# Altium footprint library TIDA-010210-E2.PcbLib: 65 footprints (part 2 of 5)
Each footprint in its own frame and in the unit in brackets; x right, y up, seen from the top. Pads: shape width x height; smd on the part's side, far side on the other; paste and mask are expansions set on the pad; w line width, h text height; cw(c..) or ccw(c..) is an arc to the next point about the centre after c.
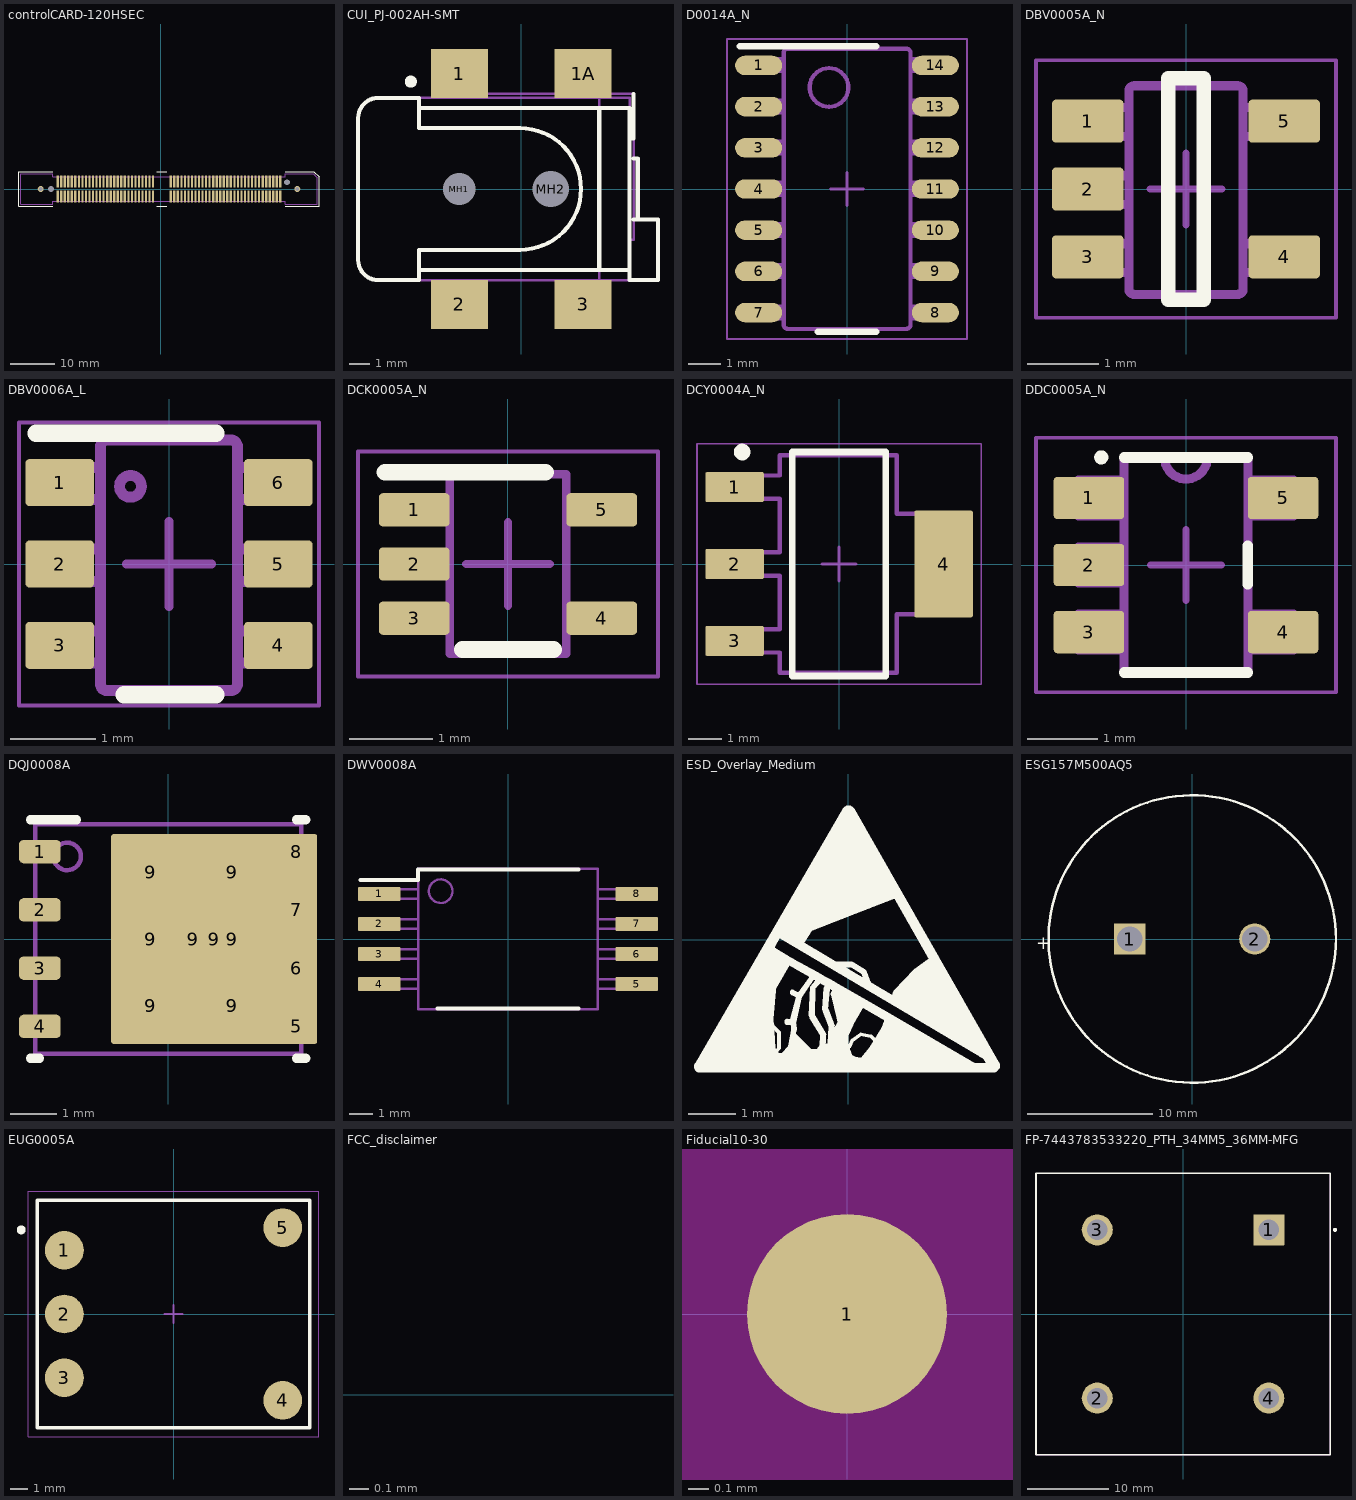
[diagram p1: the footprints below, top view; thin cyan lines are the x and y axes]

## controlCARD-120HSEC [mm] "Pads are not numbered according to Samtec datasheet."
height 7.13
pads (124):
  rect 0.5x2.724 smd: 1(-23.357,-1.678) 2(-23.357,1.722) 3(-22.557,-1.678) 4(-22.557,1.722) 5(-21.757,-1.678) 6(-21.757,1.722) 7(-20.957,-1.678) 8(-20.957,1.722) 9(-20.157,-1.678) 10(-20.157,1.722) 11(-19.357,-1.678) 12(-19.357,1.722) 13(-18.557,-1.678) 14(-18.557,1.722) 15(-17.757,-1.678) 16(-17.757,1.722) 17(-16.957,-1.678) 18(-16.957,1.722) 19(-16.157,-1.678) 20(-16.157,1.722) 21(-15.357,-1.678) 22(-15.357,1.722) 23(-14.557,-1.678) 24(-14.557,1.722) 25(-13.757,-1.678) 26(-13.757,1.722) 27(-12.957,-1.678) 28(-12.957,1.722) 29(-12.157,-1.678) 30(-12.157,1.722) 31(-11.357,-1.678) 32(-11.357,1.722) 33(-10.557,-1.678) 34(-10.557,1.722) 35(-9.757,-1.678) 36(-9.757,1.722) 37(-8.957,-1.678) 38(-8.957,1.722) 39(-8.157,-1.678) 40(-8.157,1.722) 41(-7.357,-1.678) 42(-7.357,1.722) 43(-6.557,-1.678) 44(-6.557,1.722) 45(-5.757,-1.678) 46(-5.757,1.722) 47(-4.957,-1.678) 48(-4.957,1.722) 49(-4.157,-1.678) 50(-4.157,1.722) 51(-3.357,-1.678) 52(-3.357,1.722) 53(-2.557,-1.678) 54(-2.557,1.722) 55(-1.757,-1.678) 56(-1.757,1.722) 57(2.243,-1.678) 58(2.243,1.722) 59(3.043,-1.678) 60(3.043,1.722) 61(3.843,-1.678) 62(3.843,1.722) 63(4.643,-1.678) 64(4.643,1.722) 65(5.443,-1.678) 66(5.443,1.722) 67(6.243,-1.678) 68(6.243,1.722) 69(7.043,-1.678) 70(7.043,1.722) 71(7.843,-1.678) 72(7.843,1.722) 73(8.643,-1.678) 74(8.643,1.722) 75(9.443,-1.678) 76(9.443,1.722) 77(10.243,-1.678) 78(10.243,1.722) 79(11.043,-1.678) 80(11.043,1.722) 81(11.843,-1.678) 82(11.843,1.722) 83(12.643,-1.678) 84(12.643,1.722) 85(13.443,-1.678) 86(13.443,1.722) 87(14.243,-1.678) 88(14.243,1.722) 89(15.043,-1.678) 90(15.043,1.722) 91(15.843,-1.678) 92(15.843,1.722) 93(16.643,-1.678) 94(16.643,1.722) 95(17.443,-1.678) 96(17.443,1.722) 97(18.243,-1.678) 98(18.243,1.722) 99(19.043,-1.678) 100(19.043,1.722) 101(19.843,-1.678) 102(19.843,1.722) 103(20.643,-1.678) 104(20.643,1.722) 105(21.443,-1.678) 106(21.443,1.722) 107(22.243,-1.678) 108(22.243,1.722) 109(23.043,-1.678) 110(23.043,1.722) 111(23.843,-1.678) 112(23.843,1.722) 113(24.643,-1.678) 114(24.643,1.722) 115(25.443,-1.678) 116(25.443,1.722) 117(26.243,-1.678) 118(26.243,1.722) 119(27.043,-1.678) 120(27.043,1.722)
  round 0.025 hole 1.27 unplated mask+0.876: 181(-24.857,0.022) 182(28.543,1.522)
  round 1.348 hole 0.84: 185(-27.207,0.022) 186(30.893,0.022)
Top Overlay:
  lines w0.254: -24.457,-3.859 -32.113,-3.859 -32.113,3.903 -24.457,3.903 ; -0.876,-3.859 1.362,-3.859 ; -0.876,3.903 1.362,3.903 ; 28.143,-3.859 35.799,-3.859 35.799,2.76 34.656,3.903 28.143,3.903
Mechanical 5:
  lines w0.1: -31.732,-3.478 -24.457,-3.478 -24.457,-2.778 28.143,-2.778 28.143,-3.478 35.418,-3.478 35.418,2.547 34.443,3.522 28.143,3.522 28.143,2.822 -24.457,2.822 -24.457,3.522 -31.732,3.522 -31.732,-3.478
  text ".Designator" at -1.1,-0.4 h1.02
3D body "Samtec-HSEC8-160-01-L-DV-A-BL.stp": height 12.35, standoff -1.35, extent -31.75,-3.475 35.3,3.525

## CUI_PJ-002AH-SMT [mm] "CUI"
height 11.2
pads (6):
  rect 2.8x2.4 smd: 1(-3.05,5.7) 1A(3.05,5.7) 2(-3.05,-5.7) 3(3.05,-5.7)
  round 1 hole 1.6 unplated: MH1(-3.05,0)
  round 1.524 hole 1.8 unplated: MH2(1.45,0)
Top Overlay:
  circle w0.3: c-5.45,5.3 r0.15
  lines w0.2: -7.782,4.181 cw(c-7.048,3.497) -7.467,4.409 ; -7.467,-4.409 ccw(c-7.05,-3.5) -7.337,-4.458 ccw(c-7.048,-3.492) -7.185,-4.491 ccw(c-7.05,-3.5) -7.05,-4.5 -5.05,-4.5 -5.05,-4.3 -5.05,-3 -0.05,-3 ccw(c-0.05,0) 2.95,0 ccw(c-0.05,0) -0.05,3 -5.05,3 -5.05,4.3 -5.05,4.5 -7.05,4.5 ccw(c-7.05,3.5) -7.165,4.493 ccw(c-7.048,3.491) -7.36,4.451 ccw(c-7.05,3.5) -7.426,4.427 ccw(c-7.048,3.498) -7.786,4.176 ccw(c-7.05,3.5) -8.05,3.5 -8.05,-3.5 ccw(c-7.05,-3.5) -7.782,-4.181 ccw(c-7.048,-3.498) -7.467,-4.409 ; -7.336,4.458 cw(c-7.048,3.492) -7.185,4.491 ; -5.05,-4 3.85,-4 ; -5.05,4 3.85,4 ; 5.35,2.5 5.55,2.5 5.55,4.7 ; 5.55,-1.5 5.75,-1.5 ; 5.55,1.5 5.75,1.5 5.75,-1.5 ; 3.85,-4 3.85,4 ; 3.85,-4 5.35,-4 ; 3.85,-4 3.85,4 ; 3.85,4 5.35,4 5.35,-4 ; 5.35,-4 5.35,-4.5 6.75,-4.5 6.75,-1.5 5.75,-1.5 ; -7.786,-4.177 ccw(c-7.05,-3.5) -7.426,-4.427 cw(c-7.049,-3.499) -7.786,-4.176 ; -7.36,-4.451 ccw(c-7.05,-3.5) -7.165,-4.493 cw(c-7.048,-3.491) -7.36,-4.451
Mechanical 5:
  lines w0.127: -7.782,4.181 cw(c-7.048,3.497) -7.467,4.409 ; -7.467,-4.409 ccw(c-7.05,-3.5) -7.337,-4.458 ccw(c-7.048,-3.492) -7.185,-4.491 ccw(c-7.05,-3.5) -7.05,-4.5 -5.05,-4.5 ; -7.467,-4.409 cw(c-7.048,-3.498) -7.782,-4.181 cw(c-7.05,-3.5) -8.05,-3.5 -8.05,3.5 cw(c-7.05,3.5) -7.786,4.177 cw(c-7.048,3.498) -7.426,4.427 cw(c-7.05,3.5) -7.36,4.451 cw(c-7.048,3.491) -7.165,4.493 cw(c-7.05,3.5) -7.05,4.5 -5.05,4.5 ; -7.336,4.458 cw(c-7.048,3.492) -7.185,4.491 ; -5.05,-4 3.85,-4 ; -5.05,4 3.85,4 ; -4.4,4.5 -4.4,5 -3.1,5 -3.1,4.5 ; -3.8,-4.5 -3.8,-5 ; -3.8,5 -3.8,6.3 -2.3,6.3 -2.3,4.7 ; -3.1,4.7 5.55,4.7 5.55,2.5 ; -2.3,-4.5 -2.3,-5 ; 1.8,-4.5 1.8,-5 3.8,-5 ; 2.3,-5 2.3,-6.3 3.8,-6.3 3.8,-5 ; 2.3,4.7 2.3,6.3 3.8,6.3 3.8,4.7 ; 3.8,-4.5 3.8,-5 ; 5.35,-2.5 5.55,-2.5 5.55,2.5 ; 5.35,2.5 5.55,2.5 ; 5.55,-1.5 5.75,-1.5 ; 5.55,1.5 5.75,1.5 5.75,-1.5 ; -5.05,-4.5 3.85,-4.5 ; -5.05,-4.5 -5.05,-4.3 -5.05,-3 -0.05,-3 ccw(c-0.05,0) 2.95,0 ccw(c-0.05,0) -0.05,3 -5.05,3 -5.05,4.3 -5.05,4.5 ; -5.05,4.5 3.85,4.5 ; -3.8,-5 -3.8,-6.3 -2.3,-6.3 -2.3,-5 ; -3.8,-5 -2.3,-5 ; 3.85,-4.5 3.85,-4 ; 3.85,-4.5 3.85,-4 ; 3.85,-4.5 5.35,-4.5 ; 3.85,-4 3.85,4 ; 3.85,-4 5.35,-4 ; 3.85,-4 3.85,4 ; 3.85,4 3.85,4.5 ; 3.85,4 3.85,4.5 ; 3.85,4 5.35,4 ; 3.85,4.5 5.35,4.5 5.35,4 ; 5.35,-4.5 6.75,-4.5 6.75,-1.5 5.75,-1.5 ; 5.35,-4.5 5.35,-4 ; 5.35,-4 5.35,4 ; -7.786,-4.176 ccw(c-7.049,-3.499) -7.426,-4.427 cw(c-7.05,-3.5) -7.786,-4.177 ; -7.36,-4.451 ccw(c-7.048,-3.491) -7.165,-4.493 cw(c-7.05,-3.5) -7.36,-4.451
  text ".Designator" at -1.8,-0.45 h1.02
3D body "CUI_PJ-002AH-SMT-TR.stp": height 11.2, standoff -1, extent -8.05,-6.3 6.75,6.3

## D0014A_N [mm] "SOIC, 14-Leads, Body 8.7x3.9mm, Pitch 1.27mm, IPC Medium Density"
height 1.75
pads (14):
  oval 1.45x0.6 smd: 1(-2.725,3.81) 2(-2.725,2.54) 3(-2.725,1.27) 4(-2.725,0) 5(-2.725,-1.27) 6(-2.725,-2.54) 7(-2.725,-3.81) 8(2.725,-3.81) 9(2.725,-2.54) 10(2.725,-1.27) 11(2.725,0) 12(2.725,1.27) 13(2.725,2.54) 14(2.725,3.81)
Top Overlay:
  lines w0.2: -3.3,4.4 0.9,4.4 ; -0.9,-4.4 0.9,-4.4
Mechanical 5:
  drawing of 164 lines, arcs and shapes, not listed
  text ".Designator" at -1.625,-0.45 h0.89
Mechanical 15:
  lines w0.05: -3.7,-4.625 3.7,-4.625 3.7,4.625 -3.7,4.625 -3.7,-4.625
  lines w0.1: -0.5,0 0.5,0 ; 0,-0.5 0,0.5
3D body "D0014A.stp": height 1.6, standoff 0, extent -3.022,-4.318 3.023,4.318

## DBV0005A_N [mm] "SOT23, 5-Leads, Body 2.9x1.6mm, Pitch 0.95mm, Lead Span 2.8mm, IPC Medium Density"
height 1.45
pads (5):
  rrect17% 1x0.6 smd: 1(-1.375,0.95) 2(-1.375,0) 3(-1.375,-0.95) 4(1.375,-0.95) 5(1.375,0.95)
Top Overlay:
  lines w0.2: -0.25,-1.55 0.25,-1.55 0.25,1.55 -0.25,1.55 -0.25,-1.55
Mechanical 5:
  lines w0.127: -0.801,1.371 cw(c-0.725,1.37) -0.725,1.446 ; -0.801,1.37 -0.801,-1.399 -0.801,-1.4 ccw(c-0.725,-1.399) -0.725,-1.475 ; -0.801,1.37 -0.801,1.371 ; -0.725,-1.475 -0.725,-1.475 ; -0.725,-1.475 0.723,-1.475 0.724,-1.475 ccw(c0.723,-1.399) 0.799,-1.4 0.799,-1.399 0.799,1.37 ; -0.725,1.446 0.723,1.446 0.724,1.446 cw(c0.723,1.37) 0.799,1.371 ; -0.725,1.446 -0.725,1.446 ; 0.799,1.37 0.799,1.371 ; -1.423,-1.167 -1.199,-1.167 -1.105,-1.167 -1.088,-1.167 -0.835,-1.167 -0.801,-1.167 -0.801,-0.767 -0.835,-0.767 -1.088,-0.767 -1.105,-0.767 -1.199,-0.767 -1.423,-0.767 -1.423,-1.167 ; -1.423,-0.215 -1.199,-0.215 -1.105,-0.215 -1.088,-0.215 -0.835,-0.215 -0.801,-0.215 -0.801,0.186 -0.835,0.186 -1.088,0.186 -1.105,0.186 -1.199,0.186 -1.423,0.186 -1.423,-0.215 ; -1.423,0.738 -1.199,0.738 -1.105,0.738 -1.088,0.738 -0.835,0.738 -0.801,0.738 -0.801,1.138 -0.835,1.138 -1.088,1.138 -1.105,1.138 -1.199,1.138 -1.423,1.138 -1.423,0.738 ; 0.799,-1.167 0.799,-0.767 0.834,-0.767 1.087,-0.767 1.103,-0.767 1.198,-0.767 1.422,-0.767 1.422,-1.167 1.198,-1.167 1.103,-1.167 1.087,-1.167 0.834,-1.167 0.799,-1.167 ; 0.799,0.738 0.799,1.138 0.834,1.138 1.087,1.138 1.103,1.138 1.198,1.138 1.422,1.138 1.422,0.738 1.198,0.738 1.103,0.738 1.087,0.738 0.834,0.738 0.799,0.738
  text ".Designator" at -0.25,0.95 h0.51
Mechanical 15:
  lines w0.05: -2.1,-1.8 2.1,-1.8 2.1,1.8 -2.1,1.8 -2.1,-1.8
  lines w0.1: -0.5,0 0.5,0 ; 0,-0.5 0,0.5
3D body "DBV0005A.stp": height 1.09, standoff 0, extent -1.422,-1.461 1.423,1.46

## DBV0006A_L [mm] "SOT23, 6-Leads, Body 2.9x1.6mm, Pitch 0.95mm, Lead Span 2.8mm, IPC High Density"
height 1.45
pads (6):
  rrect18% 0.8x0.55 smd: 1(-1.275,0.95) 2(-1.275,0) 3(-1.275,-0.95) 4(1.275,-0.95) 5(1.275,0) 6(1.275,0.95)
Top Overlay:
  lines w0.2: -1.55,1.525 0.55,1.525 ; -0.525,-1.525 0.55,-1.525
Mechanical 5:
  lines w0.127: 0.724,-1.475 ccw(c0.723,-1.399) 0.8,-1.399 0.8,1.37 ccw(c0.723,1.37) 0.724,1.446 ; 0.723,-1.475 -0.724,-1.475 -0.725,-1.475 cw(c-0.724,-1.399) -0.801,-1.399 -0.801,1.37 cw(c-0.724,1.37) -0.725,1.446 -0.724,1.446 0.723,1.446 ; 0.723,-1.475 0.724,-1.475 ; 0.723,1.446 0.724,1.446 ; -1.423,-1.154 -1.423,-0.78 -1.206,-0.78 -1.113,-0.78 -1.081,-0.78 -0.828,-0.78 -0.801,-0.78 -0.801,-1.154 -0.828,-1.154 -1.081,-1.154 -1.113,-1.154 -1.206,-1.154 -1.423,-1.154 ; -1.423,-0.202 -1.423,0.173 -1.206,0.173 -1.113,0.173 -1.081,0.173 -0.828,0.173 -0.801,0.173 -0.801,-0.202 -0.828,-0.202 -1.081,-0.202 -1.113,-0.202 -1.206,-0.202 -1.423,-0.202 ; -1.423,0.751 -1.423,1.125 -1.206,1.125 -1.113,1.125 -1.081,1.125 -0.828,1.125 -0.801,1.125 -0.801,0.751 -0.828,0.751 -1.081,0.751 -1.113,0.751 -1.206,0.751 -1.423,0.751 ; -0.577,0.906 ccw(c-0.45,0.906) -0.323,0.906 ccw(c-0.45,0.906) -0.577,0.906 ; 0.8,-1.154 0.8,-0.78 0.827,-0.78 1.08,-0.78 1.112,-0.78 1.205,-0.78 1.422,-0.78 1.422,-1.154 1.205,-1.154 1.112,-1.154 1.08,-1.154 0.827,-1.154 0.8,-1.154 ; 0.8,-0.202 0.8,0.173 0.827,0.173 1.08,0.173 1.112,0.173 1.205,0.173 1.422,0.173 1.422,-0.202 1.205,-0.202 1.112,-0.202 1.08,-0.202 0.827,-0.202 0.8,-0.202 ; 0.8,0.751 0.8,1.125 0.827,1.125 1.08,1.125 1.112,1.125 1.205,1.125 1.422,1.125 1.422,0.751 1.205,0.751 1.112,0.751 1.08,0.751 0.827,0.751 0.8,0.751
  text ".Designator" at -0.075,0.925 h0.51
Mechanical 15:
  lines w0.05: -1.75,-1.65 -1.75,1.65 1.75,1.65 1.75,-1.65 -1.75,-1.65
  lines w0.1: -0.5,0 0.5,0 ; 0,-0.5 0,0.5
3D body "DBV0006A.stp": height 1.12, standoff 0, extent -1.422,-1.461 1.423,1.46

## DCK0005A_N [mm] "SOT353, 5-Leads, Body 2x1.3mm, Pitch 0.65mm, Lead Span 2.1mm, IPC Medium Density"
height 1.1
pads (5):
  rrect25% 0.85x0.4 smd: 1(-1.125,0.65) 2(-1.125,0) 3(-1.125,-0.65) 4(1.125,-0.65) 5(1.125,0.65)
Top Overlay:
  lines w0.2: -1.475,1.1 0.45,1.1 ; -0.55,-1.025 0.55,-1.025
Mechanical 5:
  lines w0.1: -0.7,-1.075 0.7,-1.075 0.7,1.075 -0.7,1.075 -0.7,-1.075
  lines w0.127: -0.865,0.762 -0.853,0.762 ; -0.711,-0.763 -0.853,-0.763 -0.865,-0.763 -0.959,-0.763 -1.143,-0.763 -1.143,-0.538 -0.959,-0.538 -0.865,-0.538 -0.853,-0.538 -0.711,-0.538 ; -0.711,-0.113 -0.853,-0.113 -0.865,-0.113 -0.959,-0.113 -1.143,-0.113 -1.143,0.112 -0.959,0.112 -0.865,0.112 -0.853,0.112 -0.711,0.112 ; -0.711,0.537 -0.853,0.537 -0.865,0.537 -0.959,0.537 -1.143,0.537 -1.143,0.762 -0.959,0.762 -0.711,0.762 ; 0.711,-0.763 0.847,-0.763 0.859,-0.763 0.953,-0.763 1.137,-0.763 1.137,-0.538 0.953,-0.538 0.859,-0.538 0.847,-0.538 0.711,-0.538 ; 0.711,0.537 0.847,0.537 0.859,0.537 0.953,0.537 1.137,0.537 1.137,0.762 0.953,0.762 0.859,0.762 0.847,0.762 0.711,0.762
  text ".Designator" at -0.254,0.914 h0.51
Mechanical 15:
  lines w0.05: -1.8,-1.35 1.8,-1.35 1.8,1.35 -1.8,1.35 -1.8,-1.35
  lines w0.1: -0.5,0 0.5,0 ; 0,-0.5 0,0.5
3D body "DCK0005A.stp": height 0.95, standoff 0, extent -1.14,-1 1.14,1

## DCY0004A_N [mm] "SOT223/SC73, 4-Leads, Body 6.5x3.5mm, Pitch 2.3mm, Lead Span 7mm, IPC Medium Density"
height 1.8
pads (4):
  rrect11% 1.75x0.9 smd: 1(-3.125,2.3) 2(-3.125,0) 3(-3.125,-2.3)
  rrect6% 1.75x3.2 smd: 4(3.125,0)
Top Overlay:
  circle w0.25: c-2.9,3.35 r0.125
  lines w0.2: -1.4,-3.35 -1.4,3.35 1.4,3.35 1.4,-3.35 -1.4,-3.35
Mechanical 5:
  lines w0.127: -3.525,-2.65 -3.525,-1.95 -2.797,-1.95 -2.612,-1.95 -2.374,-1.95 -2.003,-1.95 -1.775,-1.95 -1.775,-0.35 -2.003,-0.35 -2.374,-0.35 -2.612,-0.35 -2.797,-0.35 -3.525,-0.35 -3.525,0.35 -2.797,0.35 -2.612,0.35 -2.374,0.35 -2.003,0.35 -1.775,0.35 -1.775,1.95 -2.003,1.95 -2.374,1.95 -2.612,1.95 -2.797,1.95 -3.525,1.95 -3.525,2.65 -2.797,2.65 -2.612,2.65 -2.374,2.65 -2.003,2.65 -1.775,2.65 -1.775,3.25 1.725,3.25 1.725,1.5 1.953,1.5 2.324,1.5 2.562,1.5 2.747,1.5 3.475,1.5 3.475,-1.5 2.747,-1.5 2.562,-1.5 2.324,-1.5 1.953,-1.5 1.725,-1.5 1.725,-3.25 -1.775,-3.25 -1.775,-2.65 -2.003,-2.65 -2.374,-2.65 -2.612,-2.65 -2.797,-2.65 -3.525,-2.65
  text ".Designator" at -0.425,2.5 h1.02
Mechanical 15:
  lines w0.05: -4.25,-3.6 4.25,-3.6 4.25,3.6 -4.25,3.6 -4.25,-3.6
  lines w0.1: -0.5,0 0.5,0 ; 0,-0.5 0,0.5
3D body "DCY0004A.stp": height 1.68, standoff 0, extent -3.48,-3.25 3.48,3.25

## DDC0005A_N [mm]
height 1.1
pads (5):
  rrect17% 1x0.6 smd: 1(-1.375,0.95) 2(-1.375,0) 3(-1.375,-0.95) 4(1.375,-0.95) 5(1.375,0.95)
Top Overlay:
  circle w0.1: c-1.2,1.525 r0.05
  lines w0.152: -0.876,-1.524 0.876,-1.524 ; -0.876,1.524 0.876,1.524 ; 0.876,-0.274 0.876,0.274
Mechanical 5:
  lines w0.127: -0.305,1.524 ccw(c0,1.524) 0.305,1.524 ; -1.524,-1.204 -1.524,-0.696 -0.876,-0.696 -0.876,-1.204 -1.524,-1.204 ; -1.524,-0.254 -1.524,0.254 -0.876,0.254 -0.876,-0.254 -1.524,-0.254 ; -1.524,0.696 -1.524,1.204 -0.876,1.204 -0.876,0.696 -1.524,0.696 ; -0.876,-1.524 0.876,-1.524 0.876,1.524 -0.876,1.524 -0.876,-1.524 ; 0.876,-1.204 0.876,-0.696 1.524,-0.696 1.524,-1.204 0.876,-1.204 ; 0.876,0.696 0.876,1.204 1.524,1.204 1.524,0.696 0.876,0.696
  text ".Designator" at -1.778,-0.508 h1.02
Mechanical 15:
  lines w0.05: -2.125,-1.8 2.125,-1.8 2.125,1.8 -2.125,1.8 -2.125,-1.8
  lines w0.1: -0.5,0 0.5,0 ; 0,-0.5 0,0.5
3D body "DDC0005A.stp": height 1.1, standoff 0, extent -1.405,-1.45 1.406,1.45

## DQJ0008A [mm] "SMD, 8-Leads, Body 5.75x4.9mm"
height 1.1
pads (16):
  rrect39% 0.91x0.51 smd paste-0.05 mask-0.05: 1(-2.795,1.905) 2(-2.795,0.635) 3(-2.795,-0.635) 4(-2.795,-1.905) 5(2.795,-1.905) 6(2.795,-0.635) 7(2.795,0.635) 8(2.795,1.905)
  rrect50% 1.58x1.25 on Top Paste: 9(-0.38,-1.45) 9(-0.38,0) 9(-0.38,1.45) 9(1.4,-1.45) 9(1.4,0) 9(1.4,1.45)
  rrect50% 3.48x4.47 on Top Solder: 9(0.55,0)
  rrect2% 4.49x4.57 smd paste-2.5 mask-2.5: 9(1.005,0)
Top Overlay:
  lines w0.2: -3,-2.6 -2.8,-2.6 ; -3,2.6 -2,2.6 ; 2.8,-2.6 3,-2.6 ; 2.8,2.6 3,2.6
Top Solder:
  rectangle: 2.25,0.43 2.475,0.84
  rectangle: 2.25,1.7 2.475,2.11
  rectangle: 2.25,-2.11 2.475,-1.7
  rectangle: 2.25,-0.84 2.475,-0.43
Mechanical 5:
  circle w0.1: c-2.2,1.8 r0.3
  lines w0.1: -2.9,-2.5 2.9,-2.5 2.9,2.5 -2.9,2.5 -2.9,-2.5
  text ".Designator" at -2,-0.7 h1.85
3D body "DQJ0008A.stp": height 1.15, standoff 0, extent -3.13,-2.45 3.13,2.45

## DWV0008A [mm] "SOIC, 8-Leads, Body 5.95x7.6mm (max), Pitch 1.27mm"
height 2.8
pads (8):
  rrect17% 1.8x0.6 smd: 1(-5.45,1.905) 2(-5.45,0.635) 3(-5.45,-0.635) 4(-5.45,-1.905) 5(5.45,-1.905) 6(5.45,-0.635) 7(5.45,0.635) 8(5.45,1.905)
Top Overlay:
  lines w0.17: -6.25,2.5 -3.8,2.5 -3.8,2.95 2.975,2.95 ; -2.975,-2.95 2.975,-2.95
Mechanical 5:
  circle w0.1: c-2.85,2.025 r0.5
  lines w0.1: -3.805,-2.105 -5.8,-2.105 -5.8,-1.705 -3.805,-1.705 ; -3.805,-0.835 -5.8,-0.835 -5.8,-0.435 -3.805,-0.435 ; -3.805,0.435 -5.8,0.435 -5.8,0.835 -3.805,0.835 ; -3.805,1.705 -5.8,1.705 -5.8,2.105 -3.805,2.105 ; 3.805,-2.105 5.8,-2.105 5.8,-1.705 3.805,-1.705 ; 3.805,-0.835 5.8,-0.835 5.8,-0.435 3.805,-0.435 ; 3.805,0.435 5.8,0.435 5.8,0.835 3.805,0.835 ; 3.805,1.705 5.8,1.705 5.8,2.105 3.805,2.105 ; -3.8,-2.975 -3.8,2.975 3.8,2.975 3.8,-2.975 -3.8,-2.975
  text ".Designator" at -2.8,-0.8 h1.52
3D body "DWV0008A.stp": height 2.67, standoff -0.03, extent -5.768,-2.925 5.768,2.925

## ESD_Overlay_Medium [mm]
height 27
Top Overlay:
  drawing of 6916 lines, arcs and shapes, not listed

## ESG157M500AQ5 [mm] "TH, 2-Leads, Dia 22mm, Pin Spacing 10mm"
height 45
pads (2):
  rect 2.5x2.5 hole 2: 1(-5,0)
  round 2.5 hole 2: 2(5,0)
Top Overlay:
  circle w0.2: c0,0 r11.5
  text "+" at -12.5,-0.8 h1.02
Mechanical 5:
  circle w0.1: c0,0 r11.5
  text "+" at -12.5,-0.8 h1.02
  text ".Designator" at -1.7,-0.6 h1.02
3D body "HXG_2200x4500.stp": height 47.01, standoff -4, extent -11.5,-11.495 11.51,11.495

## EUG0005A [mm] "Module, 5-Leads, Body 15.24x12.7mm"
height 8.76
pads (5):
  round 2.16 smd: 1(-6.095,3.56) 2(-6.095,0) 3(-6.095,-3.56) 4(6.095,-4.825) 5(6.095,4.825)
Top Overlay:
  circle w0.25: c-8.507,4.699 r0.125
  lines w0.2: -7.62,-6.35 -7.62,6.35 7.62,6.35 7.62,-6.35 -7.62,-6.35
Mechanical 5:
  lines w0.1: -7.63,-6.35 -7.62,6.35 7.62,6.35 7.62,-6.35 -7.62,-6.35
  text ".Designator" at -1.854,-0.508 h1.02
  text ".Designator" at -1.854,-0.508 h1.02
Mechanical 15:
  lines w0.05: -8.125,-6.86 -8.125,6.86 8.125,6.86 8.125,-6.86 -8.125,-6.86
  lines w0.1: -0.5,0 0.5,0 ; 0,-0.5 0,0.5
3D body: height 8.76, standoff 0.25, extent -7.63,-6.35 7.62,6.35

## FCC_disclaimer [mm]
height 27
Top Overlay:
  text "For evaluation only; not FCC approved for resale." at -15.928,-0.353 h1.52

## Fiducial10-30 [mm]
height 27
pads (1):
  round 1 smd mask+1: 1(0,0)
Top Layer keep-out:
  circle w1.678: c0,0 r0.75

## FP-7443783533220_PTH_34MM5_36MM-MFG [mm]
height 27
pads (4):
  rrect3% 3.8x3.8 hole 2.5 paste-1000 mask+0: 1(10.5,10.3)
  round 3.8 hole 2.5 paste-1000 mask+0: 2(-10.5,-10.3) 3(-10.5,10.3) 4(10.5,-10.3)
Top Overlay:
  circle w0.25: c18.6,10.3 r0.125
  lines w0.2: -18,-17.25 18,-17.25 18,17.25 -18,17.25 -18,-17.25
Mechanical 5:
  lines w0.1: -18,-17.25 18,-17.25 18,17.25 -18,17.25 -18,-17.25
  text ".Designator" at 0,0 h0.5
3D body "Ind_7443783533220_PTH_34MM5_36MM.STEP": height 0.25, standoff 0, extent -18.1,-17.35 18.1,17.35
